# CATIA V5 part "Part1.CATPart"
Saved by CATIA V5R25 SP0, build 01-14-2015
Part number: Part1
Bounding box of the stored display mesh (mm): x -10 to 10, y -9.957 to 9.957, z 0 to 20
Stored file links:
  E:\1-Dersler\1-GÜZ\Tek Seç 7-Bilgisayar Destekli Mühendislik Analizi\KİNEMATİK ANALİZ\kinematik uygulama 9-03112025\Part1.CATPart
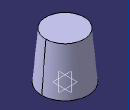
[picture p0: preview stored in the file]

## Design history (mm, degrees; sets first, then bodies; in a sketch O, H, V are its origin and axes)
Body1 (main body)
  Sketch1 on xy-plane, origin (0, 0, 0), H (1, 0, 0), V (0, 1, 0)
    circle A1 centre (0, 0) radius 10
    radius A1 = 10
  Pad1: profile Sketch1, direction (0, 0, 1), length 20
  Draft1: Angle 5, Neutral start face of Pad1, PullDir start face of Pad1, SupportToDraft face of Pad1 from Sketch1.A1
